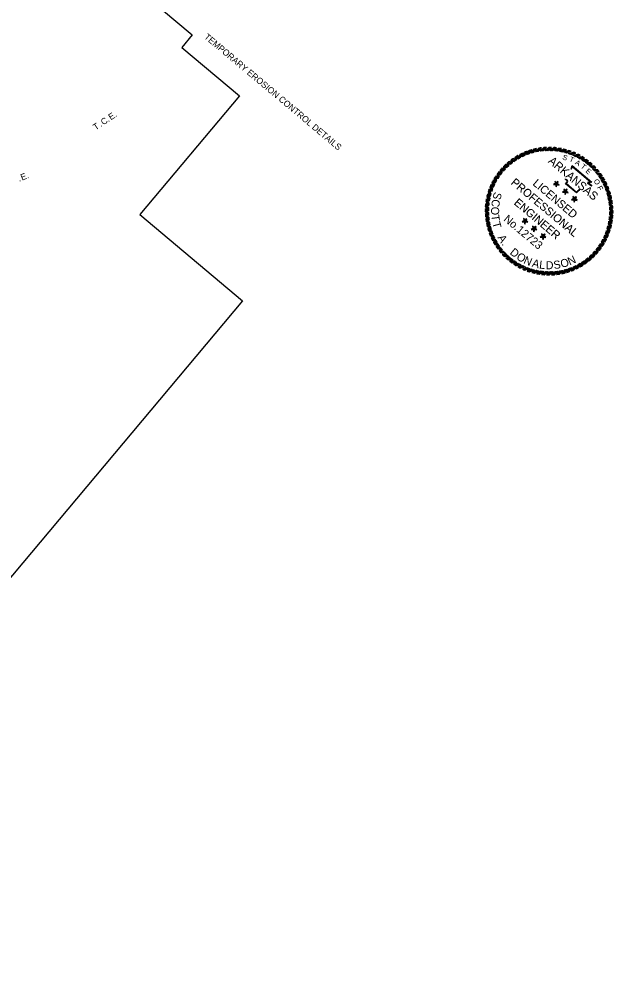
# Model space of a CAD drawing. Extents: x 1292584 to 1294692, y 222754 to 224578.
# Drawn here: x 1294127 to 1294692, y 222754 to 223658 of the extents above; entities that cross this region are included whole.
import ezdxf

# ---------------------------------------------------------------- set-up
doc = ezdxf.new("R2010")
doc.units = 0
for name, color, linetype in [('1', 7, 'Continuous'), ('Default', 7, 'Continuous'), ('R_Striping', 7, 'Continuous')]:
    doc.layers.add(name, color=color, linetype=linetype)

# ---------------------------------------------------------------- blocks, each defined once
blk = doc.blocks.new('STAR')
at = {"layer": 'Default'}
for p, q in [((0.059, 0.019), (-0.059, 0.019)), ((-0.059, 0.019), (0.036, -0.05)), ((0, 0.062), (-0.037, -0.05)), ((-0.036, -0.05), (0.059, 0.019)), ((-0.008, 0), (0.009, 0)), ((0.036, -0.05), (0, 0.062)), ((0, 0.006), (0, -0.008))]:
    blk.add_line(p, q, dxfattribs=at)
blk = doc.blocks.new('RP')
at = {"layer": 'Default'}
for p, q in [((-0.078, 1.266), (0.003, 1.33)), ((-0.058, 1.267), (0.022, 1.33)), ((-0.038, 1.267), (0.04, 1.329)), ((-0.018, 1.268), (0.059, 1.329))]:
    blk.add_line(p, q, dxfattribs=at)
for radius, start, end in [(1.268, 90.7933, 93.5307), (1.33, 87.4562, 89.8699)]:
    blk.add_arc((0, 0), radius, start, end, dxfattribs=at)

msp = doc.modelspace()

# ---------------------------------------------------------------- linework, layer by layer
at = {"layer": '1'}
msp.add_lwpolyline([(1292584.05, 223779.83), (1293254.04, 224578.3), (1294171.77, 223808.23), (1294139.92, 223770.28), (1294291.79, 223642.84), (1294281.83, 223630.97), (1294336.68, 223584.95), (1294241.87, 223471.95), (1294339.54, 223390), (1293806.17, 222754.35)], close=True, dxfattribs=at)
msp.add_lwpolyline([(1292584.05, 223779.83), (1293254.04, 224578.3), (1294171.77, 223808.23), (1294139.92, 223770.28), (1294291.79, 223642.84), (1294281.83, 223630.97), (1294336.68, 223584.95), (1294241.87, 223471.95), (1294339.54, 223390), (1293806.17, 222754.35)], close=True, dxfattribs=at)
msp.add_lwpolyline([(1292584.05, 223779.83), (1293254.04, 224578.3), (1294171.77, 223808.23), (1294139.92, 223770.28), (1294291.79, 223642.84), (1294281.83, 223630.97), (1294336.68, 223584.95), (1294241.87, 223471.95), (1294339.54, 223390), (1293806.17, 222754.35)], close=True, dxfattribs=at)
msp.add_lwpolyline([(1292584.05, 223779.83), (1293254.04, 224578.3), (1294171.77, 223808.23), (1294139.92, 223770.28), (1294291.79, 223642.84), (1294281.83, 223630.97), (1294336.68, 223584.95), (1294241.87, 223471.95), (1294339.54, 223390), (1293806.17, 222754.35)], close=True, dxfattribs=at)
msp.add_lwpolyline([(1292584.05, 223779.83), (1293254.04, 224578.3), (1294171.77, 223808.23), (1294139.92, 223770.28), (1294291.79, 223642.84), (1294281.83, 223630.97), (1294336.68, 223584.95), (1294241.87, 223471.95), (1294339.54, 223390), (1293806.17, 222754.35)], close=True, dxfattribs=at)
msp.add_lwpolyline([(1292584.05, 223779.83), (1293254.04, 224578.3), (1294171.77, 223808.23), (1294139.92, 223770.28), (1294291.79, 223642.84), (1294281.83, 223630.97), (1294336.68, 223584.95), (1294241.87, 223471.95), (1294339.54, 223390), (1293806.17, 222754.35)], close=True, dxfattribs=at)
at = {"layer": 'Default'}
for points in [[(1294652.27, 223515.21), (1294653.16, 223518.47), (1294671.95, 223502.72), (1294668.73, 223502.06), (1294670.02, 223501.01), (1294671.1, 223500.13), (1294672.07, 223499.12)], [(1294652.32, 223515.19), (1294653.22, 223518.45), (1294671.96, 223502.63), (1294668.73, 223501.99), (1294670.02, 223500.93), (1294671.09, 223500.05), (1294672.06, 223499.03)], [(1294652.65, 223515.1), (1294653.38, 223517.78), (1294671.09, 223502.94), (1294667.85, 223502.28), (1294669.77, 223500.71), (1294670.83, 223499.84), (1294671.79, 223498.85)], [(1294652.7, 223515.09), (1294653.43, 223517.76), (1294671.09, 223502.86), (1294667.85, 223502.21), (1294669.77, 223500.63), (1294670.83, 223499.76), (1294671.78, 223498.77)], [(1294660.41, 223494.97), (1294659.87, 223494.98), (1294659.44, 223494.68), (1294658.51, 223493.79), (1294657.42, 223492.49), (1294646.94, 223501.29), (1294648.41, 223503.04), (1294648.73, 223503.43), (1294648.42, 223503.92), (1294646.93, 223505.17), (1294647, 223505.8)], [(1294660.39, 223494.92), (1294659.85, 223494.93), (1294659.41, 223494.63), (1294658.49, 223493.75), (1294657.39, 223492.46), (1294646.94, 223501.29), (1294648.41, 223503.04), (1294648.74, 223503.43), (1294648.43, 223503.92), (1294646.94, 223505.17), (1294647.02, 223505.8)], [(1294660.41, 223495.36), (1294659.75, 223495.37), (1294659.19, 223494.98), (1294658.23, 223494.06), (1294657.37, 223493.04), (1294647.48, 223501.34), (1294648.71, 223502.79), (1294649.22, 223503.4), (1294648.71, 223504.18), (1294647.34, 223505.33), (1294647.39, 223505.75)], [(1294660.39, 223495.31), (1294659.73, 223495.32), (1294659.17, 223494.94), (1294658.2, 223494.02), (1294657.35, 223493), (1294647.48, 223501.34), (1294648.71, 223502.79), (1294649.22, 223503.4), (1294648.72, 223504.17), (1294647.35, 223505.33), (1294647.4, 223505.75)]]:
    msp.add_lwpolyline(points, dxfattribs=at)

# ---------------------------------------------------------------- block references
for name, p, xscale, yscale, rotation in [('RP', (1294631.37, 223475.15), 45.588276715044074, 45.58827671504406, 14.000000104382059), ('RP', (1294631.28, 223475.2), 45.58827671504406, 45.588276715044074, 13.804199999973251), ('RP', (1294631.37, 223475.15), 45.588276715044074, 45.58827671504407, 9.500000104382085), ('RP', (1294631.28, 223475.2), 45.58827671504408, 45.588276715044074, 9.304199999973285), ('RP', (1294631.37, 223475.15), 45.58827671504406, 45.58827671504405, 5.000000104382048), ('RP', (1294631.28, 223475.2), 45.58827671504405, 45.58827671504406, 4.804199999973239), ('RP', (1294631.37, 223475.15), 45.58827671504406, 45.58827671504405, 0.500000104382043), ('RP', (1294631.28, 223475.2), 45.58827671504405, 45.58827671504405, 0.3041999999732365), ('RP', (1294631.37, 223475.15), 45.58827671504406, 45.58827671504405, -3.9999998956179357), ('RP', (1294631.28, 223475.2), 45.58827671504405, 45.58827671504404, -4.195800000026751), ('RP', (1294631.37, 223475.15), 45.58827671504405, 45.58827671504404, -8.499999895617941), ('RP', (1294631.28, 223475.2), 45.58827671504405, 45.58827671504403, -8.695800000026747), ('RP', (1294631.37, 223475.15), 45.588276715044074, 45.58827671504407, -12.99999989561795), ('RP', (1294631.28, 223475.2), 45.58827671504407, 45.58827671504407, -13.195800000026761), ('RP', (1294631.37, 223475.15), 45.58827671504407, 45.588276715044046, -17.499999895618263), ('RP', (1294631.28, 223475.2), 45.58827671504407, 45.58827671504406, -17.695800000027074), ('RP', (1294631.37, 223475.15), 45.58827671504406, 45.58827671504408, 36.500000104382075), ('RP', (1294631.28, 223475.2), 45.58827671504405, 45.588276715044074, 36.30419999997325), ('RP', (1294631.37, 223475.15), 45.58827671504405, 45.58827671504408, 32.00000010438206), ('RP', (1294631.28, 223475.2), 45.58827671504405, 45.58827671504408, 31.804199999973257), ('RP', (1294631.37, 223475.15), 45.58827671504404, 45.588276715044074, 27.500000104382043), ('RP', (1294631.28, 223475.2), 45.58827671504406, 45.58827671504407, 27.30419999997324), ('RP', (1294631.37, 223475.15), 45.58827671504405, 45.58827671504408, 23.000000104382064), ('RP', (1294631.28, 223475.2), 45.58827671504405, 45.588276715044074, 22.804199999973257), ('RP', (1294631.37, 223475.15), 45.588276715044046, 45.58827671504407, 18.500000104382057), ('RP', (1294631.28, 223475.2), 45.58827671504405, 45.58827671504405, 18.30419999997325), ('RP', (1294631.37, 223475.15), 45.588276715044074, 45.58827671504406, -21.99999989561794), ('RP', (1294631.28, 223475.2), 45.588276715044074, 45.58827671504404, -22.19580000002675), ('RP', (1294631.37, 223475.15), 45.588276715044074, 45.58827671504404, -26.499999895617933), ('RP', (1294631.28, 223475.2), 45.58827671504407, 45.58827671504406, -26.69580000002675), ('RP', (1294631.37, 223475.15), 45.58827671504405, 45.58827671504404, -30.999999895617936), ('RP', (1294631.28, 223475.2), 45.58827671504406, 45.58827671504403, -31.195800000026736), ('RP', (1294631.37, 223475.15), 45.58827671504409, 45.588276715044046, -35.49999989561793), ('RP', (1294631.28, 223475.2), 45.58827671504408, 45.58827671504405, -35.69580000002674), ('RP', (1294631.37, 223475.15), 45.58827671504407, 45.58827671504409, 50.000000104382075), ('RP', (1294631.28, 223475.2), 45.58827671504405, 45.58827671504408, 49.80419999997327), ('RP', (1294631.37, 223475.15), 45.58827671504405, 45.58827671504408, 45.500000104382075), ('RP', (1294631.28, 223475.2), 45.58827671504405, 45.58827671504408, 45.30419999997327), ('RP', (1294631.37, 223475.15), 45.58827671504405, 45.588276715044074, 41.000000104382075), ('RP', (1294631.28, 223475.2), 45.58827671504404, 45.588276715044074, 40.80419999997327), ('RP', (1294631.37, 223475.15), 45.58827671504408, 45.58827671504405, -39.999999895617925), ('RP', (1294631.28, 223475.2), 45.58827671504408, 45.588276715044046, -40.19580000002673), ('RP', (1294631.37, 223475.15), 45.58827671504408, 45.58827671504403, -44.49999989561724), ('RP', (1294631.28, 223475.2), 45.588276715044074, 45.58827671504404, -44.69580000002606), ('RP', (1294631.37, 223475.15), 45.58827671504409, 45.58827671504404, -48.99999989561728), ('RP', (1294631.28, 223475.2), 45.588276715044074, 45.58827671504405, -49.19580000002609), ('RP', (1294631.28, 223475.2), 45.58827671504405, 45.58827671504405, 58.80419999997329), ('RP', (1294631.37, 223475.15), 45.588276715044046, 45.588276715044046, 59.000000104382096), ('RP', (1294631.37, 223475.15), 45.58827671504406, 45.588276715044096, 54.50000010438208), ('RP', (1294631.28, 223475.2), 45.58827671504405, 45.5882767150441, 54.30419999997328), ('RP', (1294631.37, 223475.15), 45.58827671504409, 45.58827671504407, -53.49999989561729), ('RP', (1294631.28, 223475.2), 45.58827671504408, 45.588276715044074, -53.695800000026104), ('RP', (1294631.37, 223475.15), 45.588276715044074, 45.58827671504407, -57.99999989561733), ('RP', (1294631.28, 223475.2), 45.588276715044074, 45.58827671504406, -58.19580000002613), ('RP', (1294631.28, 223475.2), 45.588276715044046, 45.58827671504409, 67.80419999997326), ('RP', (1294631.37, 223475.15), 45.58827671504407, 45.58827671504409, 68.00000010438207), ('RP', (1294631.28, 223475.2), 45.588276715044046, 45.58827671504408, 63.30419999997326), ('RP', (1294631.37, 223475.15), 45.588276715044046, 45.58827671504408, 63.50000010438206), ('STAR', (1294638.16, 223501.08), 45.58827671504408, 45.588276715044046, -40.19580000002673), ('STAR', (1294638.17, 223501.05), 45.58827671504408, 45.58827671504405, -39.999999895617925), ('STAR', (1294646.78, 223493.8), 45.58827671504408, 45.588276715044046, -40.19580000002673), ('STAR', (1294646.8, 223493.8), 45.58827671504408, 45.58827671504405, -39.999999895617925), ('RP', (1294631.37, 223475.15), 45.588276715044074, 45.58827671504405, -62.49999989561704), ('RP', (1294631.28, 223475.2), 45.588276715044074, 45.58827671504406, -62.695800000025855), ('RP', (1294631.37, 223475.15), 45.58827671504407, 45.58827671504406, -66.99999989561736), ('RP', (1294631.28, 223475.2), 45.58827671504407, 45.588276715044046, -67.19580000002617), ('RP', (1294631.28, 223475.2), 45.58827671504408, 45.588276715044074, -71.69580000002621), ('RP', (1294631.37, 223475.15), 45.58827671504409, 45.588276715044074, -71.49999989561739), ('RP', (1294631.28, 223475.2), 45.58827671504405, 45.58827671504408, 76.80419999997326), ('RP', (1294631.37, 223475.15), 45.588276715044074, 45.58827671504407, 77.00000010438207), ('RP', (1294631.28, 223475.2), 45.588276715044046, 45.58827671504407, 72.30419999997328), ('RP', (1294631.37, 223475.15), 45.588276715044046, 45.58827671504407, 72.5000001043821), ('STAR', (1294655.39, 223486.52), 45.58827671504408, 45.588276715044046, -40.19580000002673), ('STAR', (1294655.44, 223486.55), 45.58827671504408, 45.58827671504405, -39.999999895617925), ('RP', (1294631.28, 223475.2), 45.58827671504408, 45.58827671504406, -76.19580000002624), ('RP', (1294631.37, 223475.15), 45.58827671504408, 45.588276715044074, -75.99999989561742), ('RP', (1294631.37, 223475.15), 45.58827671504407, 45.588276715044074, -80.49999989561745), ('RP', (1294631.28, 223475.2), 45.588276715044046, 45.58827671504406, 85.80419999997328), ('RP', (1294631.37, 223475.15), 45.588276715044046, 45.58827671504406, 86.0000001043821), ('RP', (1294631.28, 223475.2), 45.58827671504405, 45.58827671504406, 81.30419999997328), ('RP', (1294631.37, 223475.15), 45.58827671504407, 45.58827671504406, 81.50000010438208), ('RP', (1294631.28, 223475.2), 45.58827671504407, 45.58827671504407, -80.69580000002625), ('RP', (1294631.28, 223475.2), 45.58827671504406, 45.58827671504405, -85.19580000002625), ('RP', (1294631.37, 223475.15), 45.58827671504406, 45.58827671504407, -84.99999989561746), ('RP', (1294631.28, 223475.2), 45.588276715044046, 45.58827671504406, 90.30419999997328), ('RP', (1294631.28, 223475.2), 45.58827671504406, 45.58827671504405, 94.80419999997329), ('RP', (1294631.37, 223475.15), 45.58827671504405, 45.58827671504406, 90.50000010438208), ('RP', (1294631.37, 223475.15), 45.58827671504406, 45.58827671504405, 95.0000001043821), ('RP', (1294631.28, 223475.2), 45.58827671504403, 45.588276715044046, -94.19580000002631), ('RP', (1294631.37, 223475.15), 45.588276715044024, 45.58827671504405, -93.99999989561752), ('RP', (1294631.28, 223475.2), 45.588276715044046, 45.588276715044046, -89.6958000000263), ('RP', (1294631.37, 223475.15), 45.58827671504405, 45.58827671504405, -89.49999989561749), ('RP', (1294631.28, 223475.2), 45.58827671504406, 45.58827671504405, 99.30419999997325), ('RP', (1294631.37, 223475.15), 45.58827671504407, 45.58827671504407, 99.50000010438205), ('RP', (1294631.28, 223475.2), 45.58827671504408, 45.58827671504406, 103.80419999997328), ('RP', (1294631.37, 223475.15), 45.58827671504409, 45.58827671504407, 104.00000010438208), ('STAR', (1294608.32, 223465.76), 45.58827671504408, 45.588276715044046, -40.19580000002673), ('STAR', (1294608.44, 223465.63), 45.58827671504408, 45.58827671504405, -39.999999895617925), ('STAR', (1294616.94, 223458.48), 45.58827671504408, 45.588276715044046, -40.19580000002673), ('STAR', (1294617.08, 223458.38), 45.58827671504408, 45.58827671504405, -39.999999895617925), ('RP', (1294631.28, 223475.2), 45.588276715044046, 45.58827671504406, -103.19580000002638), ('RP', (1294631.37, 223475.15), 45.58827671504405, 45.588276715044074, -102.99999989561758), ('RP', (1294631.28, 223475.2), 45.58827671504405, 45.58827671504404, -98.69580000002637), ('RP', (1294631.37, 223475.15), 45.588276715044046, 45.58827671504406, -98.49999989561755), ('RP', (1294631.28, 223475.2), 45.58827671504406, 45.588276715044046, 108.30419999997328), ('RP', (1294631.37, 223475.15), 45.58827671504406, 45.58827671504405, 108.50000010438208), ('RP', (1294631.28, 223475.2), 45.58827671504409, 45.58827671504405, 112.80419999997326), ('RP', (1294631.37, 223475.15), 45.588276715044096, 45.58827671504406, 113.00000010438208), ('STAR', (1294625.55, 223451.2), 45.58827671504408, 45.588276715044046, -40.19580000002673), ('STAR', (1294625.72, 223451.13), 45.58827671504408, 45.58827671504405, -39.999999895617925), ('RP', (1294631.28, 223475.2), 45.588276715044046, 45.588276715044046, -116.69580000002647), ('RP', (1294631.37, 223475.15), 45.58827671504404, 45.588276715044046, -116.49999989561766), ('RP', (1294631.28, 223475.2), 45.58827671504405, 45.588276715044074, -112.19580000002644), ('RP', (1294631.37, 223475.15), 45.58827671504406, 45.58827671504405, -111.99999989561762), ('RP', (1294631.28, 223475.2), 45.58827671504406, 45.58827671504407, -107.69580000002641), ('RP', (1294631.37, 223475.15), 45.58827671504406, 45.58827671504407, -107.49999989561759), ('RP', (1294631.28, 223475.2), 45.58827671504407, 45.58827671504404, 117.3041999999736), ('RP', (1294631.37, 223475.15), 45.58827671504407, 45.588276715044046, 117.50000010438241), ('RP', (1294631.28, 223475.2), 45.588276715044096, 45.588276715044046, 121.80419999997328), ('RP', (1294631.37, 223475.15), 45.588276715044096, 45.588276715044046, 122.00000010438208), ('RP', (1294631.28, 223475.2), 45.58827671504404, 45.58827671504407, -125.69580000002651), ('RP', (1294631.37, 223475.15), 45.58827671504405, 45.58827671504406, -125.4999998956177), ('RP', (1294631.28, 223475.2), 45.588276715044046, 45.58827671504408, -121.1958000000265), ('RP', (1294631.37, 223475.15), 45.58827671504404, 45.588276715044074, -120.99999989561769), ('RP', (1294631.28, 223475.2), 45.588276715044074, 45.58827671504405, 126.30419999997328), ('RP', (1294631.37, 223475.15), 45.58827671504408, 45.588276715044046, 126.50000010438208), ('RP', (1294631.28, 223475.2), 45.58827671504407, 45.588276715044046, 130.8041999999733), ('RP', (1294631.37, 223475.15), 45.58827671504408, 45.58827671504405, 131.00000010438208), ('RP', (1294631.28, 223475.2), 45.58827671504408, 45.588276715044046, 135.30419999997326), ('RP', (1294631.37, 223475.15), 45.58827671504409, 45.58827671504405, 135.50000010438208), ('RP', (1294631.28, 223475.2), 45.58827671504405, 45.58827671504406, -134.69580000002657), ('RP', (1294631.37, 223475.15), 45.58827671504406, 45.588276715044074, -134.49999989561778), ('RP', (1294631.28, 223475.2), 45.588276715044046, 45.58827671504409, -130.19580000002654), ('RP', (1294631.37, 223475.15), 45.58827671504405, 45.58827671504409, -129.99999989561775), ('RP', (1294631.28, 223475.2), 45.58827671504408, 45.588276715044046, 139.80419999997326), ('RP', (1294631.37, 223475.15), 45.588276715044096, 45.58827671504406, 140.00000010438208), ('RP', (1294631.28, 223475.2), 45.588276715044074, 45.58827671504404, 144.30419999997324), ('RP', (1294631.37, 223475.15), 45.58827671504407, 45.588276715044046, 144.50000010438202), ('RP', (1294631.28, 223475.2), 45.58827671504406, 45.58827671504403, 148.80419999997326), ('RP', (1294631.37, 223475.15), 45.58827671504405, 45.58827671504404, 149.00000010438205), ('RP', (1294631.28, 223475.2), 45.58827671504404, 45.588276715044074, -152.69580000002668), ('RP', (1294631.37, 223475.15), 45.588276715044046, 45.58827671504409, -152.4999998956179), ('RP', (1294631.28, 223475.2), 45.588276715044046, 45.58827671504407, -148.19580000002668), ('RP', (1294631.37, 223475.15), 45.588276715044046, 45.58827671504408, -147.99999989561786), ('RP', (1294631.28, 223475.2), 45.58827671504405, 45.58827671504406, -143.69580000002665), ('RP', (1294631.37, 223475.15), 45.58827671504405, 45.588276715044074, -143.49999989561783), ('RP', (1294631.28, 223475.2), 45.58827671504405, 45.588276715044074, -139.1958000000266), ('RP', (1294631.37, 223475.15), 45.58827671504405, 45.58827671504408, -138.99999989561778), ('RP', (1294631.28, 223475.2), 45.588276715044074, 45.58827671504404, 153.30419999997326), ('RP', (1294631.37, 223475.15), 45.58827671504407, 45.58827671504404, 153.50000010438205), ('RP', (1294631.28, 223475.2), 45.588276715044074, 45.58827671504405, 157.8041999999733), ('RP', (1294631.37, 223475.15), 45.58827671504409, 45.58827671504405, 158.00000010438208), ('RP', (1294631.28, 223475.2), 45.58827671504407, 45.58827671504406, 162.3041999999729), ('RP', (1294631.37, 223475.15), 45.58827671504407, 45.58827671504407, 162.50000010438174), ('RP', (1294631.28, 223475.2), 45.58827671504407, 45.58827671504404, 166.8041999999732), ('RP', (1294631.37, 223475.15), 45.58827671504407, 45.58827671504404, 167.00000010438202), ('RP', (1294631.28, 223475.2), 45.58827671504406, 45.588276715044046, 171.30419999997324), ('RP', (1294631.37, 223475.15), 45.58827671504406, 45.58827671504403, 171.50000010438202), ('RP', (1294631.28, 223475.2), 45.58827671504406, 45.58827671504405, 175.80419999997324), ('RP', (1294631.37, 223475.15), 45.588276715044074, 45.58827671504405, 176.00000010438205), ('RP', (1294631.28, 223475.2), 45.58827671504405, 45.58827671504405, -179.69580000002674), ('RP', (1294631.37, 223475.15), 45.58827671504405, 45.58827671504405, -179.49999989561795), ('RP', (1294631.28, 223475.2), 45.58827671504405, 45.58827671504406, -175.19580000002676), ('RP', (1294631.37, 223475.15), 45.58827671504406, 45.58827671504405, -174.99999989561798), ('RP', (1294631.28, 223475.2), 45.58827671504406, 45.58827671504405, -170.6958000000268), ('RP', (1294631.37, 223475.15), 45.58827671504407, 45.58827671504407, -170.499999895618), ('RP', (1294631.28, 223475.2), 45.58827671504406, 45.58827671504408, -166.19580000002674), ('RP', (1294631.37, 223475.15), 45.588276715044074, 45.58827671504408, -165.99999989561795), ('RP', (1294631.28, 223475.2), 45.58827671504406, 45.588276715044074, -161.6958000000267), ('RP', (1294631.37, 223475.15), 45.58827671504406, 45.58827671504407, -161.49999989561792), ('RP', (1294631.28, 223475.2), 45.58827671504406, 45.58827671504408, -157.1958000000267), ('RP', (1294631.37, 223475.15), 45.58827671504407, 45.58827671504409, -156.99999989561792)]:
    msp.add_blockref(name, p, dxfattribs=dict(at, xscale=xscale, yscale=yscale, rotation=rotation))

# ---------------------------------------------------------------- texts
for s, height, rotation, p in [('ARKANSAS', 7.894, 320, (1294629.8, 223521.81)), ('ARKANSAS', 7.894, 319.8042, (1294629.87, 223521.86)), ('S', 4.84, 339.77256, (1294643.53, 223524.65)), ('S', 4.84, 339.57676, (1294643.61, 223524.66)), ('T', 4.84, 336.90148, (1294650.01, 223522.81)), ('T', 4.84, 336.70568, (1294650.09, 223522.8)), ('A', 4.84, 328.67877, (1294655.5, 223520.21)), ('A', 4.84, 328.48297, (1294655.56, 223520.18)), ('T', 4.84, 321.47887, (1294660.9, 223516.93)), ('T', 4.84, 321.28307, (1294660.95, 223516.88)), ('E', 4.84, 316.67203, (1294665.55, 223512.84)), ('E', 4.84, 316.47623, (1294665.59, 223512.78)), ('PROFESSIONAL', 7.6424, 319.8042, (1294594.35, 223501.41)), ('PROFESSIONAL', 7.6424, 320, (1294594.35, 223501.23)), ('LICENSED', 7.642, 319.8042, (1294615.11, 223500.6)), ('LICENSED', 7.642, 320, (1294615.11, 223500.49)), ('O', 4.84, 301.2218, (1294673.48, 223504.02)), ('O', 4.84, 301.026, (1294673.49, 223503.93)), ('F', 4.84, 295.16702, (1294676.82, 223497.78)), ('F', 4.84, 295.36282, (1294676.83, 223497.88)), ('S', 7.64, 253.94855, (1294579.28, 223493.93)), ('C', 7.64, 261.49729, (1294577.26, 223486.93)), ('ENGINEER', 7.642, 319.8042, (1294597.22, 223482.25)), ('ENGINEER', 7.642, 320, (1294597.28, 223482.08)), ('O', 7.64, 269.42346, (1294576.16, 223479.35)), ('T', 7.64, 277.72707, (1294576.13, 223471.34)), ('No.12723', 7.612, 320, (1294587.42, 223466.57)), ('T', 7.64, 285.27581, (1294577.11, 223464.11)), ('A', 7.64, 300.75072, (1294582.02, 223450.04)), ('.', 7.64, 308.29946, (1294585.75, 223443.77)), ('D', 7.64, 320.37744, (1294593.33, 223434.93)), ('O', 7.64, 328.68105, (1294599.54, 223429.85)), ('N', 7.64, 336.98466, (1294606.41, 223425.73)), ('A', 7.64, 346.04314, (1294614.51, 223422.42)), ('L', 7.64, 353.59188, (1294621.58, 223420.66)), ('D', 7.64, 0.38575, (1294628.09, 223419.89)), ('S', 7.64, 8.68936, (1294636.11, 223420)), ('O', 7.64, 16.23809, (1294643.32, 223421.1)), ('N', 7.64, 24.5417, (1294651, 223423.39))]:
    msp.add_text(s, height=height, rotation=rotation, dxfattribs=at).set_placement(p)
at = {"layer": 'R_Striping'}
for s, rotation, p in [('TEMPORARY EROSION CONTROL DETAILS', 320, (1294302.63, 223640.02)), ('C', 33.48443, (1294207.21, 223556.71)), ('E', 33.48443, (1294214.39, 223561.45)), ('.', 33.48443, (1294211.94, 223559.84)), ('.', 33.48443, (1294218.88, 223564.42)), ('T', 33.48443, (1294199.88, 223551.86)), ('.', 33.48443, (1294204.77, 223555.09)), ('E', 21.6622, (1294129.88, 223504.17)), ('.', 21.6622, (1294134.89, 223506.16)), ('.', 21.6622, (1294127.16, 223503.09))]:
    msp.add_text(s, height=6, rotation=rotation, dxfattribs=at).set_placement(p)

doc.saveas('drawing.dxf')
